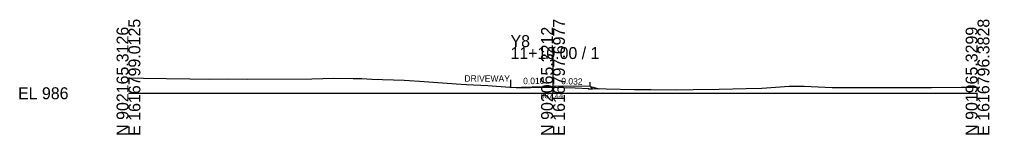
# Model space of a CAD drawing. Extents: x -26 to 1403, y -10 to 3025.
# Drawn here: x 1174.3 to 1402.8, y -9.7 to 17.3 of the extents above; entities that cross this region are included whole.
import ezdxf

# ---------------------------------------------------------------- set-up
doc = ezdxf.new("R2010")
doc.units = 0
for name, color, linetype in [('Exist Cross Section Cell', 7, 'Continuous'), ('Exist XS Center Line Elevation Label', 7, 'Continuous'), ('Exist XS Ground Line', 7, 'Continuous'), ('Prop XS EOT Tick Mark', 7, 'Continuous'), ('Prop XS Finish Grade', 7, 'Continuous'), ('Prop XS Finish Grade Pavement', 7, 'Continuous'), ('Prop XS Pvmt Edge Slope', 7, 'Continuous'), ('Prop XS SE Text', 7, 'Continuous'), ('Prop XS SS Elevation Text', 7, 'Continuous'), ('Prop XS Subgrade Earthwork', 7, 'Continuous')]:
    doc.layers.add(name, color=color, linetype=linetype)

msp = doc.modelspace()

# ---------------------------------------------------------------- linework, layer by layer
at = {"layer": 'Exist Cross Section Cell'}
for p, q in [((1300, 0), (1300, 10.84)), ((1200, 0), (1300, 0)), ((1300, 0), (1400, 0))]:
    msp.add_line(p, q, dxfattribs=at)
at = {"layer": 'Exist XS Ground Line'}
for p, q in [((1200, 3.61), (1203.52, 3.57)), ((1203.52, 3.57), (1208.97, 3.49)), ((1208.97, 3.49), (1214.42, 3.41)), ((1214.42, 3.41), (1218.97, 3.33)), ((1218.97, 3.33), (1223.47, 3.35)), ((1223.47, 3.35), (1228.03, 3.31)), ((1228.03, 3.31), (1243.19, 3.4)), ((1243.19, 3.4), (1248.35, 3.57)), ((1248.35, 3.57), (1252.95, 3.47)), ((1252.95, 3.47), (1255, 3.43)), ((1255, 3.43), (1257.34, 3.34)), ((1257.34, 3.34), (1264.92, 3.07)), ((1264.92, 3.07), (1266.14, 2.98)), ((1266.14, 2.98), (1268.54, 2.84)), ((1268.54, 2.84), (1276.14, 2.29)), ((1276.14, 2.29), (1277.22, 2.21)), ((1277.22, 2.21), (1279.59, 2.03)), ((1279.59, 2.03), (1284.66, 1.8)), ((1284.66, 1.8), (1289.8, 1.4)), ((1289.8, 1.4), (1291.29, 1.35)), ((1291.29, 1.35), (1294.67, 1.39)), ((1294.67, 1.39), (1299.98, 1.45)), ((1299.98, 1.45), (1305.21, 1.24)), ((1305.21, 1.24), (1308.47, 1.11)), ((1308.47, 1.11), (1312.52, 1.05)), ((1312.52, 1.05), (1319.16, 0.91)), ((1319.16, 0.91), (1323.13, 0.9)), ((1323.13, 0.9), (1329.16, 0.83)), ((1329.16, 0.83), (1333.01, 0.91)), ((1333.01, 0.91), (1339.16, 0.97)), ((1339.16, 0.97), (1345.48, 1.09)), ((1345.48, 1.09), (1349.16, 1.17)), ((1349.16, 1.17), (1355.61, 1.63)), ((1355.61, 1.63), (1359.16, 1.67)), ((1359.16, 1.67), (1365.75, 1.35)), ((1365.75, 1.35), (1369.16, 1.36)), ((1369.16, 1.36), (1372.49, 1.37)), ((1372.49, 1.37), (1379.17, 1.33)), ((1379.17, 1.33), (1382.36, 1.34)), ((1382.36, 1.34), (1389.17, 1.36)), ((1389.17, 1.36), (1396.15, 1.41)), ((1396.15, 1.41), (1399.17, 1.44)), ((1399.17, 1.44), (1400, 1.45))]:
    msp.add_line(p, q, dxfattribs=at)
at = {"layer": 'Prop XS EOT Tick Mark'}
for p, q in [((1290.1, 1.39), (1290.1, 3.14)), ((1308.73, 1.6), (1308.73, 2.6))]:
    msp.add_line(p, q, dxfattribs=at)
at = {"layer": 'Prop XS Finish Grade'}
msp.add_line((1308.73, 1.6), (1310.85, 1.07), dxfattribs=at)
at = {"layer": 'Prop XS Finish Grade Pavement'}
for p in [(1290.1, 1.39), (1308.73, 1.6)]:
    msp.add_line(p, (1300, 1.69), dxfattribs=at)
at = {"layer": 'Prop XS Pvmt Edge Slope'}
msp.add_line((1308.73, 1.6), (1309.33, 1), dxfattribs=at)
at = {"layer": 'Prop XS Subgrade Earthwork'}
for p, q in [((1308.31, 1.03), (1308.31, 1.12)), ((1308.31, 1.03), (1308.73, 1.02)), ((1308.73, 1.02), (1309.33, 1))]:
    msp.add_line(p, q, dxfattribs=at)

# ---------------------------------------------------------------- texts
at = {"layer": 'Exist Cross Section Cell'}
for s, p in [('E 1616799.0125', (1202.8, -10)), ('E 1616797.6977', (1302.8, -10)), ('E 1616796.3828', (1402.8, -10)), ('N 902165.3126', (1200, -10)), ('N 902065.3212', (1300, -10)), ('N 901965.3299', (1400, -10))]:
    msp.add_text(s, height=2.8, rotation=90, dxfattribs=at).set_placement(p)
for s, p in [('Y8', (1290, 10.84)), ('11+10.00 / 1', (1290, 8.04)), ('EL 986', (1174, -1.4))]:
    msp.add_text(s, height=2.8, dxfattribs=at).set_placement(p)
at = {"layer": 'Exist XS Center Line Elevation Label'}
msp.add_text('987.44', height=1.25, dxfattribs=at).set_placement((1297.1, -1.18))
at = {"layer": 'Prop XS SE Text'}
for s, rotation, p in [('0.010', 0.5729, (1292.97, 2.12)), ('0.032', 358.1604, (1301.92, 2.13))]:
    msp.add_text(s, height=1.5, rotation=rotation, dxfattribs=at).set_placement(p)
at = {"layer": 'Prop XS SS Elevation Text'}
msp.add_text('DRIVEWAY', height=1.5, dxfattribs=at).set_placement((1279.14, 2.71))

doc.saveas('drawing.dxf')
